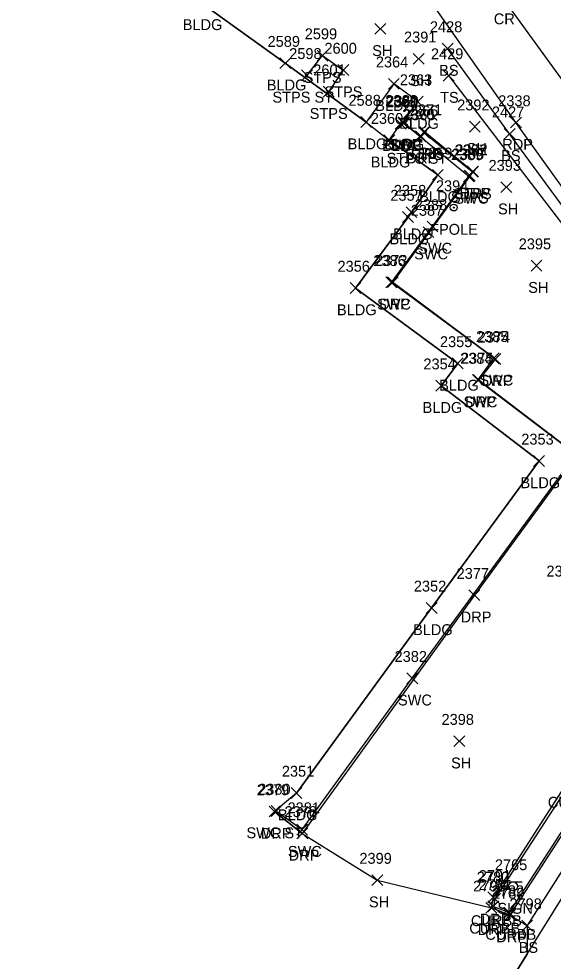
# Model space of a CAD drawing. Extents: x 1638344 to 1639591, y 610835 to 612202.
# Drawn here: x 1638979.2 to 1639077.4, y 611209.2 to 611382.3 of the extents above; entities that cross this region are included whole.
import ezdxf

# ---------------------------------------------------------------- set-up
doc = ezdxf.new("R2010")
doc.units = 0
for name, color, linetype in [('L_A', 7, 'Continuous'), ('L_I', 7, 'Continuous'), ('L_TIC', 7, 'Continuous'), ('LBC', 7, 'Continuous'), ('LBF', 7, 'Continuous'), ('LELB', 7, 'Continuous'), ('LFP', 7, 'Continuous'), ('LSOGP', 7, 'Continuous'), ('P_A', 7, 'Continuous'), ('P_I', 7, 'Continuous'), ('P_TIC', 7, 'Continuous'), ('PET', 7, 'Continuous'), ('PRC', 7, 'Continuous'), ('R_A', 7, 'Continuous'), ('R_I', 7, 'Continuous'), ('R_TIC', 7, 'Continuous'), ('RC', 7, 'Continuous'), ('RDP', 7, 'Continuous'), ('RSW', 7, 'Continuous'), ('S_A', 7, 'Continuous'), ('S_I', 7, 'Continuous'), ('SSGN', 7, 'Continuous')]:
    doc.layers.add(name, color=color, linetype=linetype)

msp = doc.modelspace()

# ---------------------------------------------------------------- linework, layer by layer
at = {"layer": 'L_TIC'}
for points in [[(1639044.6, 611379.47), (1639046.6, 611381.47)], [(1639046.6, 611379.47), (1639044.6, 611381.47)], [(1639056.96, 611375.85), (1639058.96, 611377.85)], [(1639058.96, 611375.85), (1639056.96, 611377.85)], [(1639033.97, 611374.55), (1639035.97, 611376.55)], [(1639035.97, 611374.55), (1639033.97, 611376.55)], [(1639051.64, 611373.96), (1639053.64, 611375.96)], [(1639053.64, 611373.96), (1639051.64, 611375.96)], [(1639027.13, 611373.16), (1639029.13, 611375.16)], [(1639029.13, 611373.16), (1639027.13, 611375.16)], [(1639031.11, 611370.92), (1639033.11, 611372.92)], [(1639033.11, 611370.92), (1639031.11, 611372.92)], [(1639037.79, 611371.9), (1639039.79, 611373.9)], [(1639039.79, 611371.9), (1639037.79, 611373.9)], [(1639057.16, 611370.88), (1639059.16, 611372.88)], [(1639059.16, 611370.88), (1639057.16, 611372.88)], [(1639047.07, 611369.38), (1639049.07, 611371.37)], [(1639049.07, 611369.38), (1639047.07, 611371.37)], [(1639035.09, 611367.92), (1639037.09, 611369.92)], [(1639037.09, 611367.92), (1639035.09, 611369.92)], [(1639051.48, 611366.11), (1639053.48, 611368.11)], [(1639053.48, 611366.11), (1639051.48, 611368.11)], [(1639041.99, 611362.34), (1639043.99, 611364.34)], [(1639043.99, 611362.34), (1639041.99, 611364.34)], [(1639048.34, 611362.03), (1639050.34, 611364.03)], [(1639050.34, 611362.03), (1639048.34, 611364.03)], [(1639048.78, 611362.31), (1639050.78, 611364.31)], [(1639050.78, 611362.31), (1639048.78, 611364.31)], [(1639052.64, 611360.39), (1639054.64, 611362.39)], [(1639054.64, 611360.39), (1639052.64, 611362.39)], [(1639061.96, 611361.49), (1639063.96, 611363.49)], [(1639063.96, 611361.49), (1639061.96, 611363.49)], [(1639068.35, 611360.19), (1639070.35, 611362.19)], [(1639070.35, 611360.19), (1639068.35, 611362.19)], [(1639046.23, 611359.01), (1639048.23, 611361.01)], [(1639048.23, 611359.01), (1639046.23, 611361.01)], [(1639052.09, 611359.69), (1639054.09, 611361.69)], [(1639054.09, 611359.69), (1639052.09, 611361.69)], [(1639061.55, 611353.22), (1639063.55, 611355.22)], [(1639063.55, 611353.22), (1639061.55, 611355.22)], [(1639055.15, 611352.65), (1639057.15, 611354.65)], [(1639057.15, 611352.65), (1639055.15, 611354.65)], [(1639061.03, 611352.49), (1639063.03, 611354.49)], [(1639063.03, 611352.49), (1639061.03, 611354.49)], [(1639067.74, 611350.39), (1639069.74, 611352.39)], [(1639069.74, 611350.39), (1639067.74, 611352.39)], [(1639049.69, 611344.89), (1639051.69, 611346.89)], [(1639051.69, 611344.89), (1639049.69, 611346.89)], [(1639050.32, 611345.8), (1639052.32, 611347.8)], [(1639052.32, 611345.8), (1639050.32, 611347.8)], [(1639073.28, 611335.97), (1639075.28, 611337.97)], [(1639075.28, 611335.97), (1639073.28, 611337.97)], [(1639040.03, 611331.87), (1639042.03, 611333.86)], [(1639042.03, 611331.87), (1639040.03, 611333.86)], [(1639058.81, 611318.01), (1639060.81, 611320.01)], [(1639060.81, 611318.01), (1639058.81, 611320.01)], [(1639055.76, 611313.92), (1639057.76, 611315.92)], [(1639057.76, 611313.92), (1639055.76, 611315.92)], [(1639073.76, 611300.1), (1639075.76, 611302.1)], [(1639075.76, 611300.1), (1639073.76, 611302.1)], [(1639054.01, 611273.11), (1639056.01, 611275.11)], [(1639056.01, 611273.11), (1639054.01, 611275.11)], [(1639059.1, 611248.63), (1639061.1, 611250.63)], [(1639061.1, 611248.63), (1639059.1, 611250.63)], [(1639029.18, 611239.11), (1639031.18, 611241.11)], [(1639031.18, 611239.11), (1639029.18, 611241.11)], [(1639044.02, 611223.11), (1639046.02, 611225.11)], [(1639046.02, 611223.11), (1639044.02, 611225.11)], [(1639071.57, 611214.75), (1639073.57, 611216.75)], [(1639073.57, 611214.75), (1639071.57, 611216.75)]]:
    msp.add_lwpolyline(points, dxfattribs=at)
at = {"layer": 'LBC'}
msp.add_lwpolyline([(1639030.18, 611240.11), (1639055.01, 611274.11), (1639074.76, 611301.1), (1639056.76, 611314.92), (1639059.81, 611319.01), (1639041.03, 611332.86), (1639050.69, 611345.89), (1639051.32, 611346.8), (1639056.15, 611353.65), (1639047.23, 611360.01), (1639049.34, 611363.03), (1639049.78, 611363.31), (1639052.48, 611367.11), (1639048.07, 611370.38), (1639042.99, 611363.34), (1639028.13, 611374.16), (1639012.69, 611385.24), (1638995.76, 611397.43), (1638992.44, 611393.68), (1638983.02, 611400.9)], dxfattribs=at)
at = {"layer": 'LBF'}
for points in [[(1639032.11, 611371.92), (1639034.97, 611375.55), (1639038.79, 611372.9), (1639036.09, 611368.92)], [(1639053.09, 611360.69), (1639053.64, 611361.39), (1639062.55, 611354.22), (1639062.03, 611353.49)]]:
    msp.add_lwpolyline(points, dxfattribs=at)
at = {"layer": 'LELB'}
for points in [[(1639107.91, 611306.54), (1639092.17, 611330.06), (1639069.35, 611361.19), (1639057.96, 611376.85)], [(1639107.51, 611305.33), (1639087.16, 611334.08), (1639058.16, 611371.88)], [(1639113.24, 611281.92), (1639107.57, 611270.22), (1639091.43, 611245.42), (1639072.56, 611215.75)]]:
    msp.add_lwpolyline(points, dxfattribs=at)
at = {"layer": 'LFP'}
for radius in [0.625, 0.0833]:
    msp.add_circle((1639059.07, 611347.64), radius, dxfattribs=at)
at = {"layer": 'LSOGP'}
msp.add_lwpolyline([(1639012.69, 611385.24), (1639028.13, 611374.16), (1639042.99, 611363.34), (1639047.23, 611360.01), (1639056.15, 611353.65), (1639051.32, 611346.8), (1639050.69, 611345.89), (1639041.03, 611332.86), (1639059.81, 611319.01), (1639056.76, 611314.92), (1639074.76, 611301.1), (1639055.01, 611274.11), (1639030.18, 611240.11), (1639026.15, 611236.71), (1639031.25, 611232.69), (1639045.02, 611224.11), (1639065.99, 611219.02), (1639069.41, 611217.7), (1639072.56, 611215.75), (1639072.57, 611210.54), (1639068.59, 611204.17)], dxfattribs=at)
at = {"layer": 'P_TIC'}
for points in [[(1639069.52, 611362.26), (1639071.52, 611364.26)], [(1639071.52, 611362.26), (1639069.52, 611364.26)]]:
    msp.add_lwpolyline(points, dxfattribs=at)
at = {"layer": 'PET'}
for points in [[(1639117.36, 611283.38), (1639114.12, 611301.89), (1639095.51, 611328.5), (1639070.51, 611363.26), (1639041.38, 611404.69), (1639011.58, 611446.4), (1638984.33, 611485.15), (1638954.17, 611527.5), (1638934.33, 611554.77), (1638918.88, 611575.58), (1638893.27, 611605.67), (1638868.12, 611629.84), (1638836.66, 611652.85), (1638812.43, 611667.64)], [(1638854.83, 610853.22), (1638885.37, 610909), (1638902.82, 610937.28), (1638929.33, 610982.56), (1638950.92, 611019.42), (1638971.29, 611051.92), (1639000.04, 611096.97), (1639023.57, 611133.7), (1639039.12, 611159.19), (1639064.62, 611197.79), (1639080.51, 611223.3), (1639114.23, 611277.34), (1639131.17, 611302.28), (1639149.64, 611331.79), (1639176.42, 611372.36), (1639193.48, 611398.88)]]:
    msp.add_lwpolyline(points, dxfattribs=at)
at = {"layer": 'PRC'}
msp.add_lwpolyline([(1638818.79, 611678.84), (1638843.98, 611663.35), (1638876.44, 611637.39), (1638906.24, 611607.19), (1638934.14, 611573.69), (1638965.31, 611531.43), (1638998.82, 611484.34), (1639033.82, 611434.48), (1639068.01, 611386.3), (1639093.94, 611350.49), (1639111.89, 611325.38), (1639129.23, 611302.77)], dxfattribs=at)
at = {"layer": 'R_TIC'}
for points in [[(1639048.88, 611362.1), (1639050.88, 611364.1)], [(1639050.88, 611362.1), (1639048.88, 611364.1)], [(1639049, 611362.21), (1639051, 611364.21)], [(1639051, 611362.21), (1639049, 611364.21)], [(1639052.7, 611360.6), (1639054.7, 611362.6)], [(1639054.7, 611360.6), (1639052.7, 611362.6)], [(1639051.92, 611359.76), (1639053.92, 611361.76)], [(1639053.92, 611359.76), (1639051.92, 611361.76)], [(1639061.63, 611353.26), (1639063.63, 611355.26)], [(1639063.63, 611353.26), (1639061.63, 611355.26)], [(1639060.85, 611352.35), (1639062.85, 611354.35)], [(1639062.85, 611352.35), (1639060.85, 611354.35)], [(1639054.18, 611343.17), (1639056.18, 611345.17)], [(1639056.18, 611343.17), (1639054.18, 611345.17)], [(1639053.45, 611342.13), (1639055.45, 611344.13)], [(1639055.45, 611342.13), (1639053.45, 611344.13)], [(1639046.62, 611332.9), (1639048.62, 611334.89)], [(1639048.62, 611332.9), (1639046.62, 611334.89)], [(1639046.89, 611332.93), (1639048.89, 611334.93)], [(1639048.89, 611332.93), (1639046.89, 611334.93)], [(1639065.44, 611318.95), (1639067.44, 611320.95)], [(1639067.44, 611318.95), (1639065.44, 611320.95)], [(1639065.74, 611318.84), (1639067.74, 611320.84)], [(1639067.74, 611318.84), (1639065.74, 611320.84)], [(1639062.67, 611314.97), (1639064.67, 611316.97)], [(1639064.67, 611314.97), (1639062.67, 611316.97)], [(1639062.52, 611314.95), (1639064.52, 611316.95)], [(1639064.52, 611314.95), (1639062.52, 611316.95)], [(1639061.87, 611275.44), (1639063.87, 611277.44)], [(1639063.87, 611275.44), (1639061.87, 611277.44)], [(1639050.47, 611260.19), (1639052.47, 611262.19)], [(1639052.47, 611260.19), (1639050.47, 611262.19)], [(1639025.14, 611235.71), (1639027.14, 611237.71)], [(1639027.14, 611235.71), (1639025.14, 611237.71)], [(1639025.5, 611235.8), (1639027.5, 611237.8)], [(1639027.5, 611235.8), (1639025.5, 611237.8)], [(1639030.23, 611232.38), (1639032.23, 611234.38)], [(1639032.23, 611232.38), (1639030.23, 611234.38)], [(1639030.25, 611231.69), (1639032.25, 611233.69)], [(1639032.25, 611231.69), (1639030.25, 611233.69)], [(1639065.36, 611219.94), (1639067.36, 611221.94)], [(1639067.36, 611219.94), (1639065.36, 611221.94)], [(1639065.36, 611218.28), (1639067.36, 611220.28)], [(1639067.36, 611218.28), (1639065.36, 611220.28)], [(1639065.66, 611219.66), (1639067.66, 611221.66)], [(1639067.66, 611219.66), (1639065.66, 611221.66)], [(1639064.99, 611218.02), (1639066.99, 611220.02)], [(1639066.99, 611218.02), (1639064.99, 611220.02)], [(1639068.3, 611217.15), (1639070.3, 611219.15)], [(1639070.3, 611217.15), (1639068.3, 611219.15)], [(1639068.41, 611216.7), (1639070.41, 611218.7)], [(1639070.41, 611216.7), (1639068.41, 611218.7)]]:
    msp.add_lwpolyline(points, dxfattribs=at)
at = {"layer": 'RC'}
msp.add_lwpolyline([(1639104.86, 611279.43), (1639092.74, 611260.85), (1639080.78, 611242.42), (1639066.66, 611220.66), (1639066.36, 611219.28), (1639069.3, 611218.15), (1639083.89, 611240.69), (1639098.16, 611263.06), (1639106.12, 611275.73)], dxfattribs=at)
at = {"layer": 'RDP'}
for points in [[(1639050, 611363.21), (1639052.92, 611360.76), (1639053.7, 611361.6), (1639062.63, 611354.26), (1639047.89, 611333.93), (1639066.74, 611319.84), (1639063.67, 611315.97), (1639081.74, 611302.23), (1639062.87, 611276.44), (1639031.25, 611232.69), (1639026.15, 611236.71)], [(1639106.5, 611275.32), (1639098.47, 611262.74), (1639084.17, 611240.47), (1639069.41, 611217.7), (1639065.99, 611219.02), (1639066.36, 611220.94), (1639080.5, 611242.81), (1639092.36, 611261.08), (1639105.01, 611280.57)]]:
    msp.add_lwpolyline(points, dxfattribs=at)
at = {"layer": 'RSW'}
msp.add_lwpolyline([(1639026.5, 611236.8), (1639031.23, 611233.38), (1639051.47, 611261.19), (1639081.49, 611302.26), (1639063.52, 611315.95), (1639066.44, 611319.95), (1639047.62, 611333.9), (1639054.45, 611343.13), (1639055.18, 611344.17), (1639061.85, 611353.35), (1639049.88, 611363.09)], dxfattribs=at)
at = {"layer": 'SSGN'}
for p, q in [((1639068.32, 611223.79), (1639071.65, 611223.79)), ((1639069.97, 611222.95), (1639069.97, 611222.95))]:
    msp.add_line(p, q, dxfattribs=at)
msp.add_circle((1639069.97, 611222.95), 0.833, dxfattribs=at)

# ---------------------------------------------------------------- texts
at = {"layer": 'L_A'}
for s, p in [('BLDG', (1639009.28, 611380.24)), ('SH', (1639044.09, 611375.47)), ('STPS', (1639031.49, 611370.55)), ('BS', (1639056.4, 611371.85)), ('BLDG', (1639024.72, 611369.16)), ('SH', (1639051.13, 611369.96)), ('STPS ST', (1639025.76, 611366.92)), ('STPS', (1639035.31, 611367.9)), ('TS', (1639056.57, 611366.88)), ('BLDG', (1639044.66, 611365.38)), ('STPS', (1639032.61, 611363.92)), ('BLDG', (1639049.07, 611362.11)), ('BLDG', (1639039.58, 611358.34)), ('BLDG', (1639046.37, 611358.31)), ('BLDG', (1639045.93, 611358.03)), ('SH', (1639061.45, 611357.49)), ('BLDG', (1639043.82, 611355.01)), ('STPS ST', (1639046.74, 611355.69)), ('STPS', (1639050.16, 611356.39)), ('BS', (1639067.79, 611356.19)), ('BLDG', (1639052.74, 611348.65)), ('STPS', (1639058.55, 611348.49)), ('STPS', (1639059.07, 611349.22)), ('SH', (1639067.22, 611346.39)), ('FPOLE', (1639054.74, 611342.64)), ('BLDG', (1639047.92, 611341.8)), ('BLDG', (1639047.28, 611340.89)), ('SH', (1639072.77, 611331.97)), ('BLDG', (1639037.62, 611327.86)), ('BLDG', (1639056.4, 611314.01)), ('BLDG', (1639053.36, 611309.92)), ('BLDG', (1639071.35, 611296.1)), ('BLDG', (1639051.6, 611269.11)), ('SH', (1639058.59, 611244.63)), ('BLDG', (1639026.77, 611235.11)), ('SH', (1639043.5, 611219.11)), ('BS', (1639071.01, 611210.75))]:
    msp.add_text(s, height=2, dxfattribs=at).set_placement(p)
at = {"layer": 'L_I'}
for s, p in [('2428', (1639054.7, 611379.85)), ('2599', (1639031.7, 611378.55)), ('2391', (1639049.94, 611377.96)), ('2589', (1639024.87, 611377.16)), ('2600', (1639035.32, 611375.9)), ('2598', (1639028.85, 611374.92)), ('2429', (1639054.89, 611374.88)), ('2364', (1639044.77, 611373.38)), ('2601', (1639033.27, 611371.92)), ('2363', (1639049.17, 611370.11)), ('2588', (1639039.73, 611366.34)), ('2362', (1639046.48, 611366.31)), ('2361', (1639046.6, 611366.03)), ('2392', (1639059.71, 611365.49)), ('2365', (1639049.79, 611363.69)), ('2366', (1639050.28, 611364.39)), ('2427', (1639066.09, 611364.19)), ('2360', (1639043.84, 611363.01)), ('2359', (1639052.88, 611356.65)), ('2368', (1639058.72, 611356.49)), ('2367', (1639059.24, 611357.22)), ('2393', (1639065.48, 611354.39)), ('2358', (1639048.07, 611349.8)), ('2394', (1639055.81, 611350.64)), ('2357', (1639047.43, 611348.89)), ('2395', (1639071.02, 611339.97)), ('2356', (1639037.72, 611335.86)), ('2355', (1639056.55, 611322.01)), ('2354', (1639053.51, 611317.92)), ('2353', (1639071.5, 611304.1)), ('2397', (1639076.12, 611279.87)), ('2352', (1639051.75, 611277.11)), ('2398', (1639056.84, 611252.63)), ('2351', (1639027.49, 611243.11)), ('2399', (1639041.75, 611227.11)), ('2798', (1639069.31, 611218.75))]:
    msp.add_text(s, height=2, dxfattribs=at).set_placement(p)
at = {"layer": 'P_A'}
for s, p in [('CR', (1639066.44, 611381.3)), ('RDP', (1639068, 611358.26))]:
    msp.add_text(s, height=2, dxfattribs=at).set_placement(p)
at = {"layer": 'P_I'}
msp.add_text('2338', height=2, dxfattribs=at).set_placement((1639067.26, 611366.26))
at = {"layer": 'R_A'}
for s, p in [('SWC', (1639047.24, 611358.09)), ('DRP', (1639047.49, 611358.21)), ('DRP', (1639051.19, 611356.6)), ('DRP', (1639050.41, 611355.76)), ('SWC', (1639059.21, 611348.35)), ('DRP', (1639060.12, 611349.26)), ('SWC', (1639052.54, 611339.17)), ('SWC', (1639051.81, 611338.13)), ('SWC', (1639044.99, 611328.9)), ('DRP', (1639045.38, 611328.92)), ('SWC', (1639063.8, 611314.95)), ('DRP', (1639064.23, 611314.84)), ('SWC', (1639060.88, 611310.95)), ('DRP', (1639061.16, 611310.97)), ('DRP', (1639060.36, 611271.44)), ('SWC', (1639048.83, 611256.19)), ('CURBB', (1639076.37, 611237.42)), ('SWC ST', (1639020.99, 611231.8)), ('DRP', (1639023.63, 611231.71)), ('SWC', (1639028.6, 611228.38)), ('DRP', (1639028.74, 611227.69)), ('CURBB', (1639062.24, 611215.66)), ('DRP', (1639063.85, 611215.94)), ('CURBB', (1639061.94, 611214.28)), ('DRP', (1639063.48, 611214.02)), ('CURBB', (1639064.88, 611213.15)), ('DRP', (1639066.9, 611212.7))]:
    msp.add_text(s, height=2, dxfattribs=at).set_placement(p)
at = {"layer": 'R_I'}
for s, p in [('2390', (1639046.53, 611366.09)), ('2369', (1639046.69, 611366.21)), ('2370', (1639049.58, 611363.76)), ('2371', (1639051.01, 611364.6)), ('2372', (1639059.37, 611357.26)), ('2389', (1639058.58, 611356.35)), ('2387', (1639051.19, 611346.13)), ('2388', (1639051.92, 611347.17)), ('2386', (1639044.31, 611336.9)), ('2373', (1639044.63, 611336.93)), ('2385', (1639063.18, 611322.95)), ('2374', (1639063.48, 611322.84)), ('2384', (1639060.26, 611318.95)), ('2375', (1639060.41, 611318.97)), ('2377', (1639059.61, 611279.44)), ('2382', (1639048.21, 611264.19)), ('2379', (1639022.88, 611239.71)), ('2380', (1639023.15, 611239.8)), ('2378', (1639027.99, 611235.69)), ('2381', (1639028.54, 611236.38)), ('2780', (1639063.31, 611223.66)), ('2791', (1639063.67, 611223.94)), ('2790', (1639062.64, 611222.02)), ('2781', (1639063.67, 611222.28)), ('2782', (1639066.04, 611221.15)), ('2789', (1639066.14, 611220.7))]:
    msp.add_text(s, height=2, dxfattribs=at).set_placement(p)
at = {"layer": 'S_A'}
msp.add_text('SIGN', height=2, dxfattribs=at).set_placement((1639067.1, 611217.93))
at = {"layer": 'S_I'}
msp.add_text('2765', height=2, dxfattribs=at).set_placement((1639066.64, 611225.93))

doc.saveas('drawing.dxf')
